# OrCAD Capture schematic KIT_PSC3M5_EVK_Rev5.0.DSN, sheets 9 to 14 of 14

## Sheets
9 08. COMMUNICATION AND PROGRAM: size A4
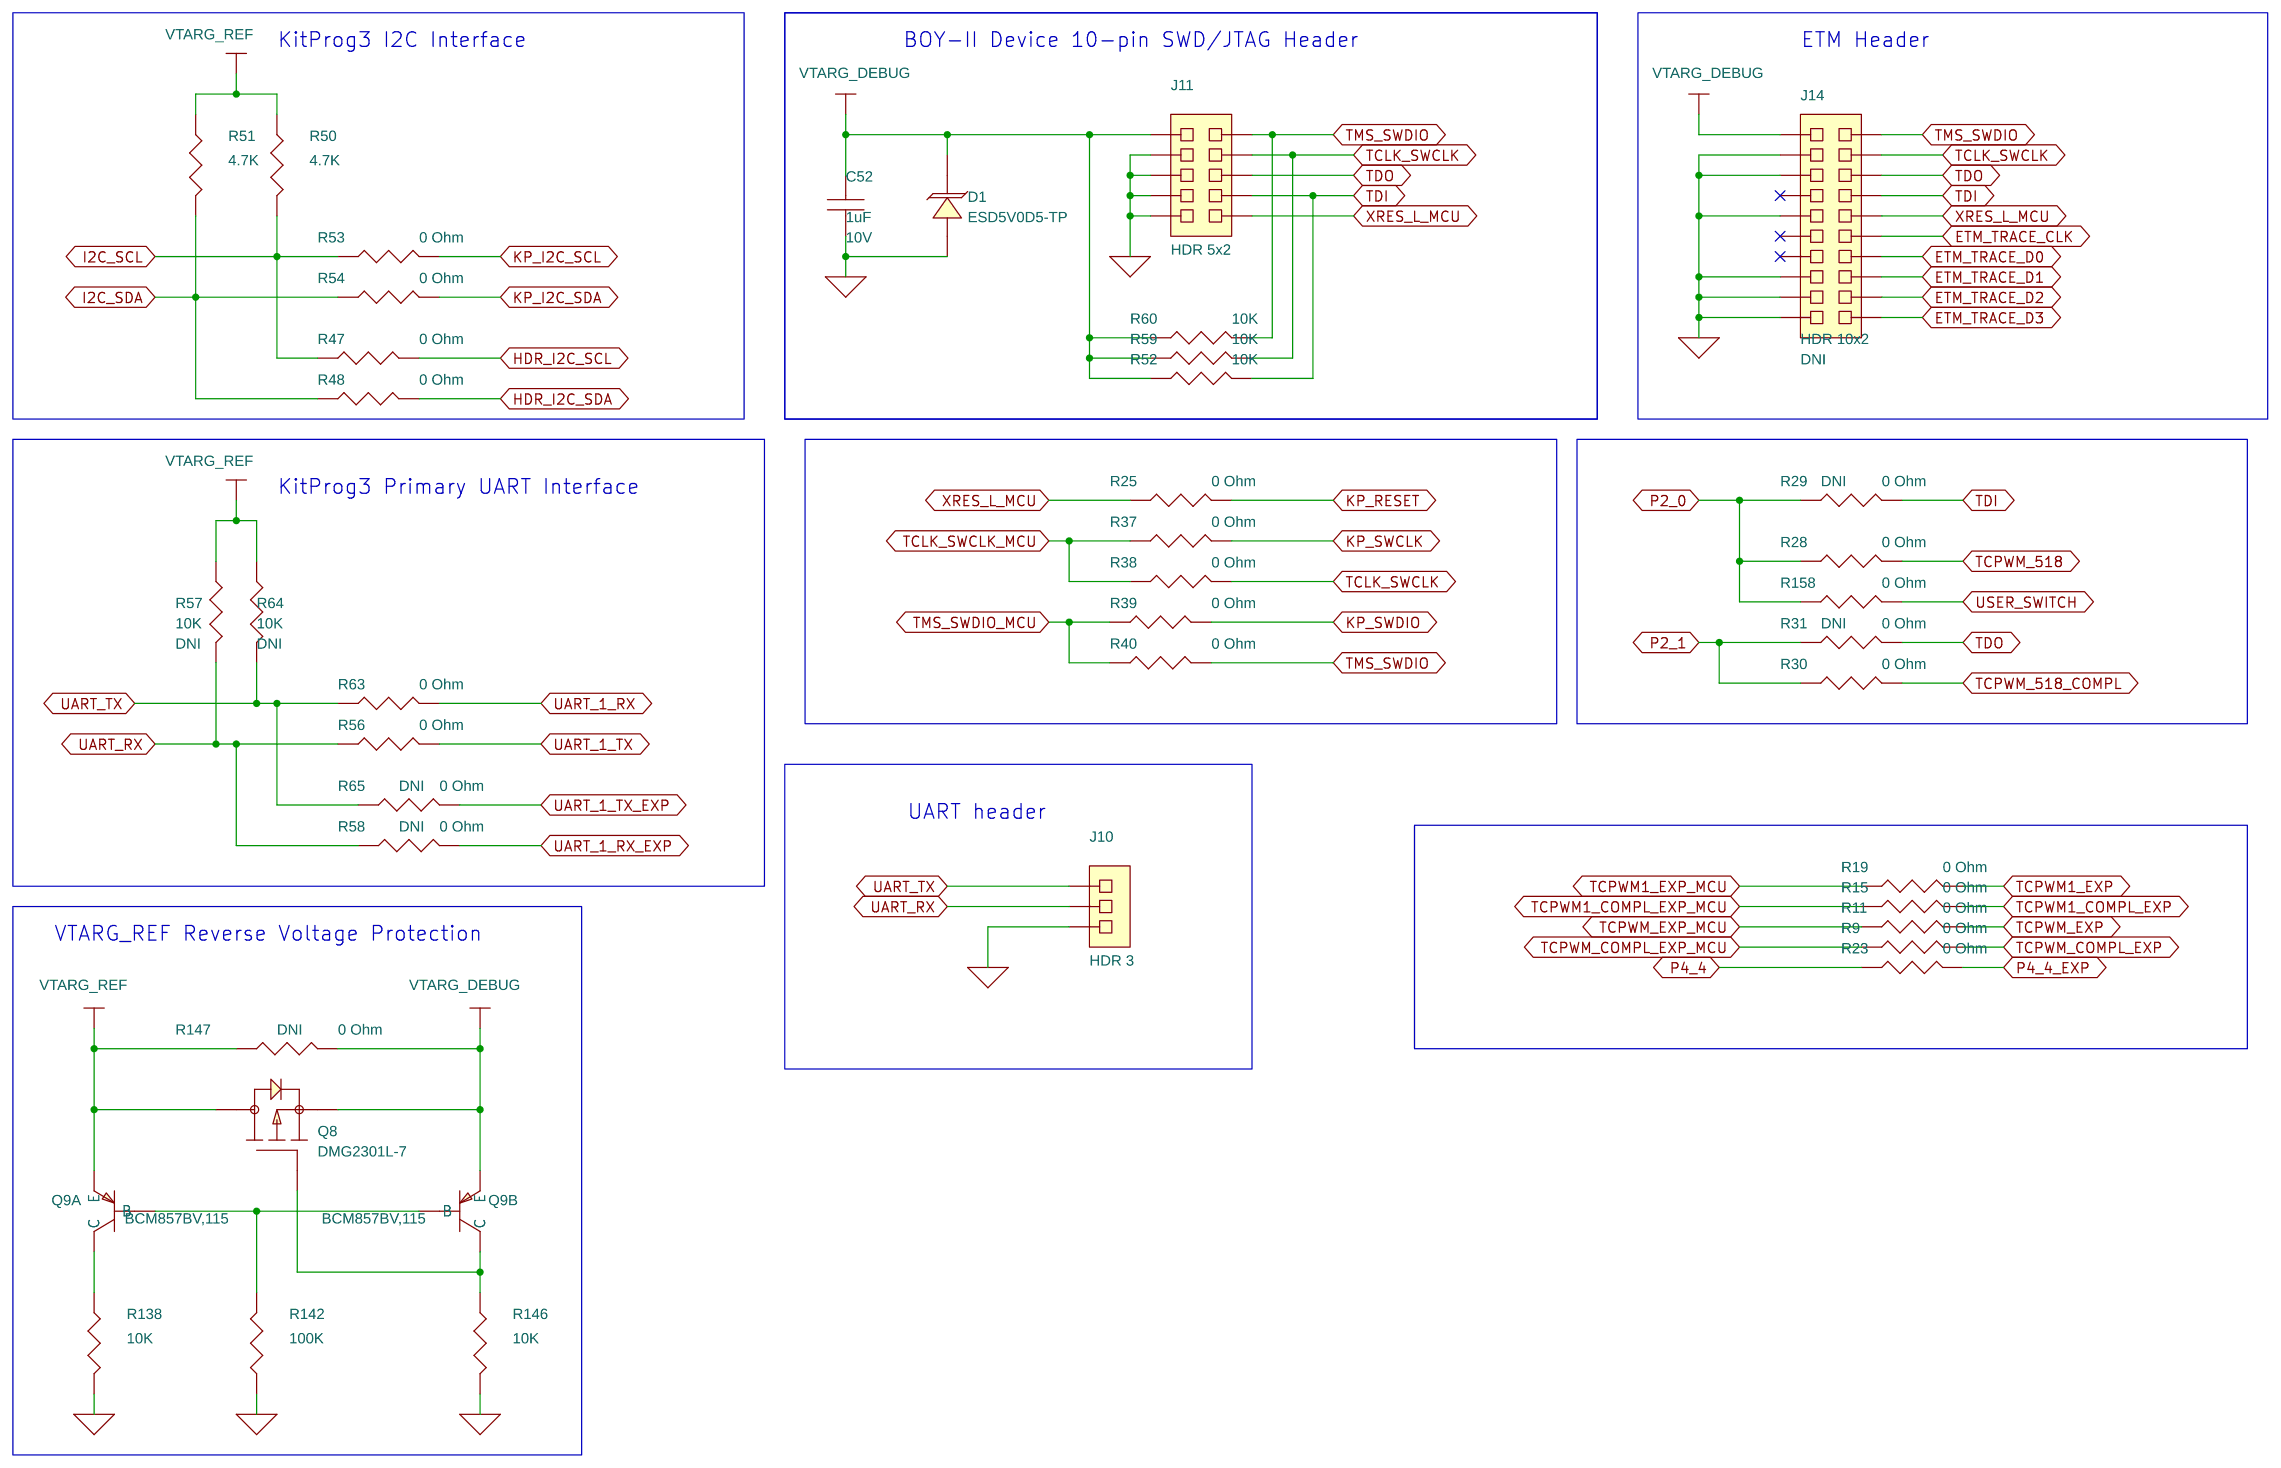
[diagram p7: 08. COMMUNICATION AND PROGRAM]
10 09. CAN INTERFACE: size A4
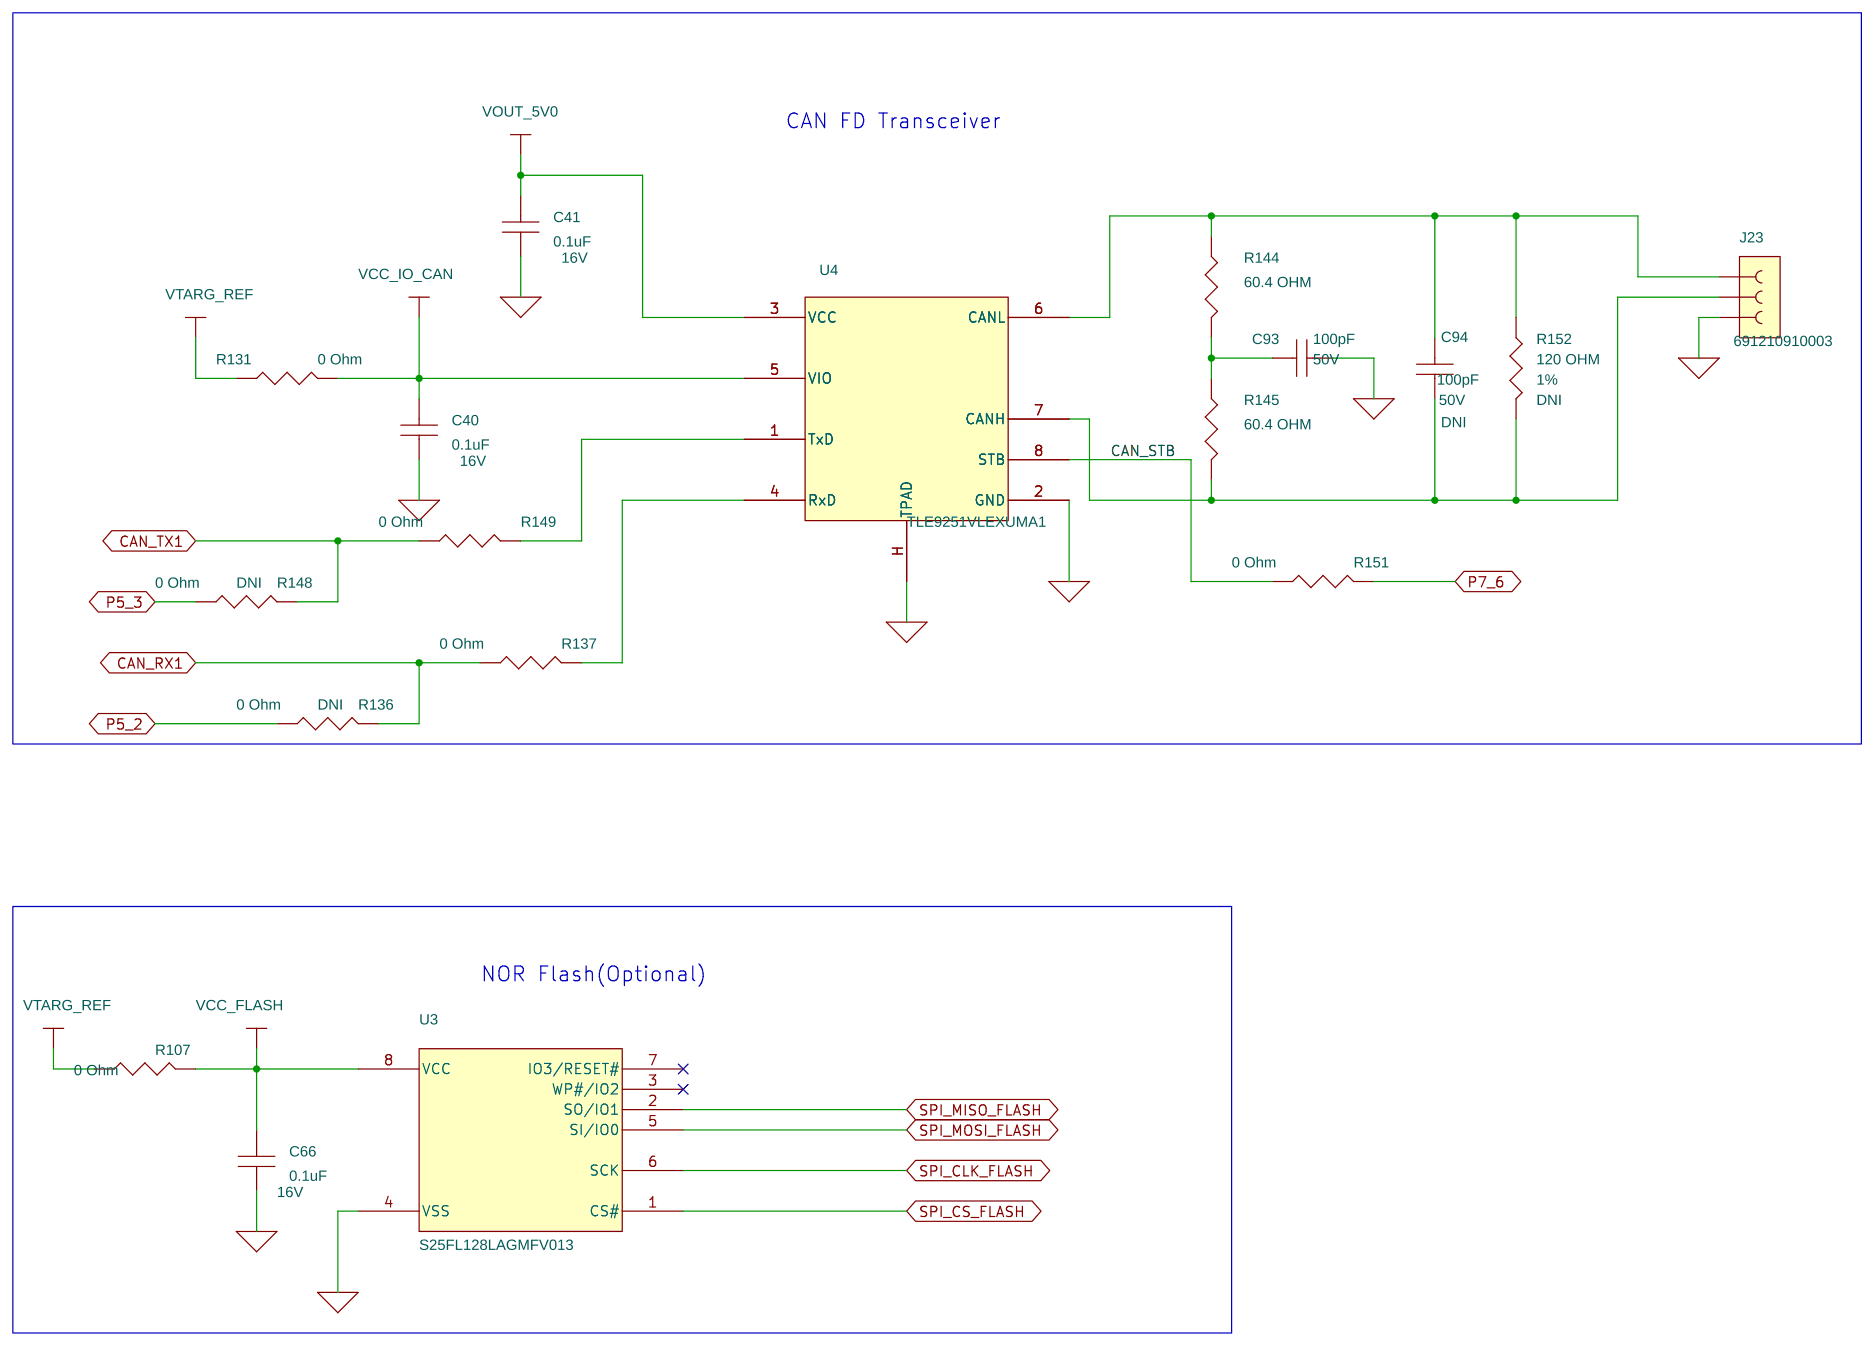
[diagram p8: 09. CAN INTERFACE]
11 10. INTERFACE HEADERS: size A4
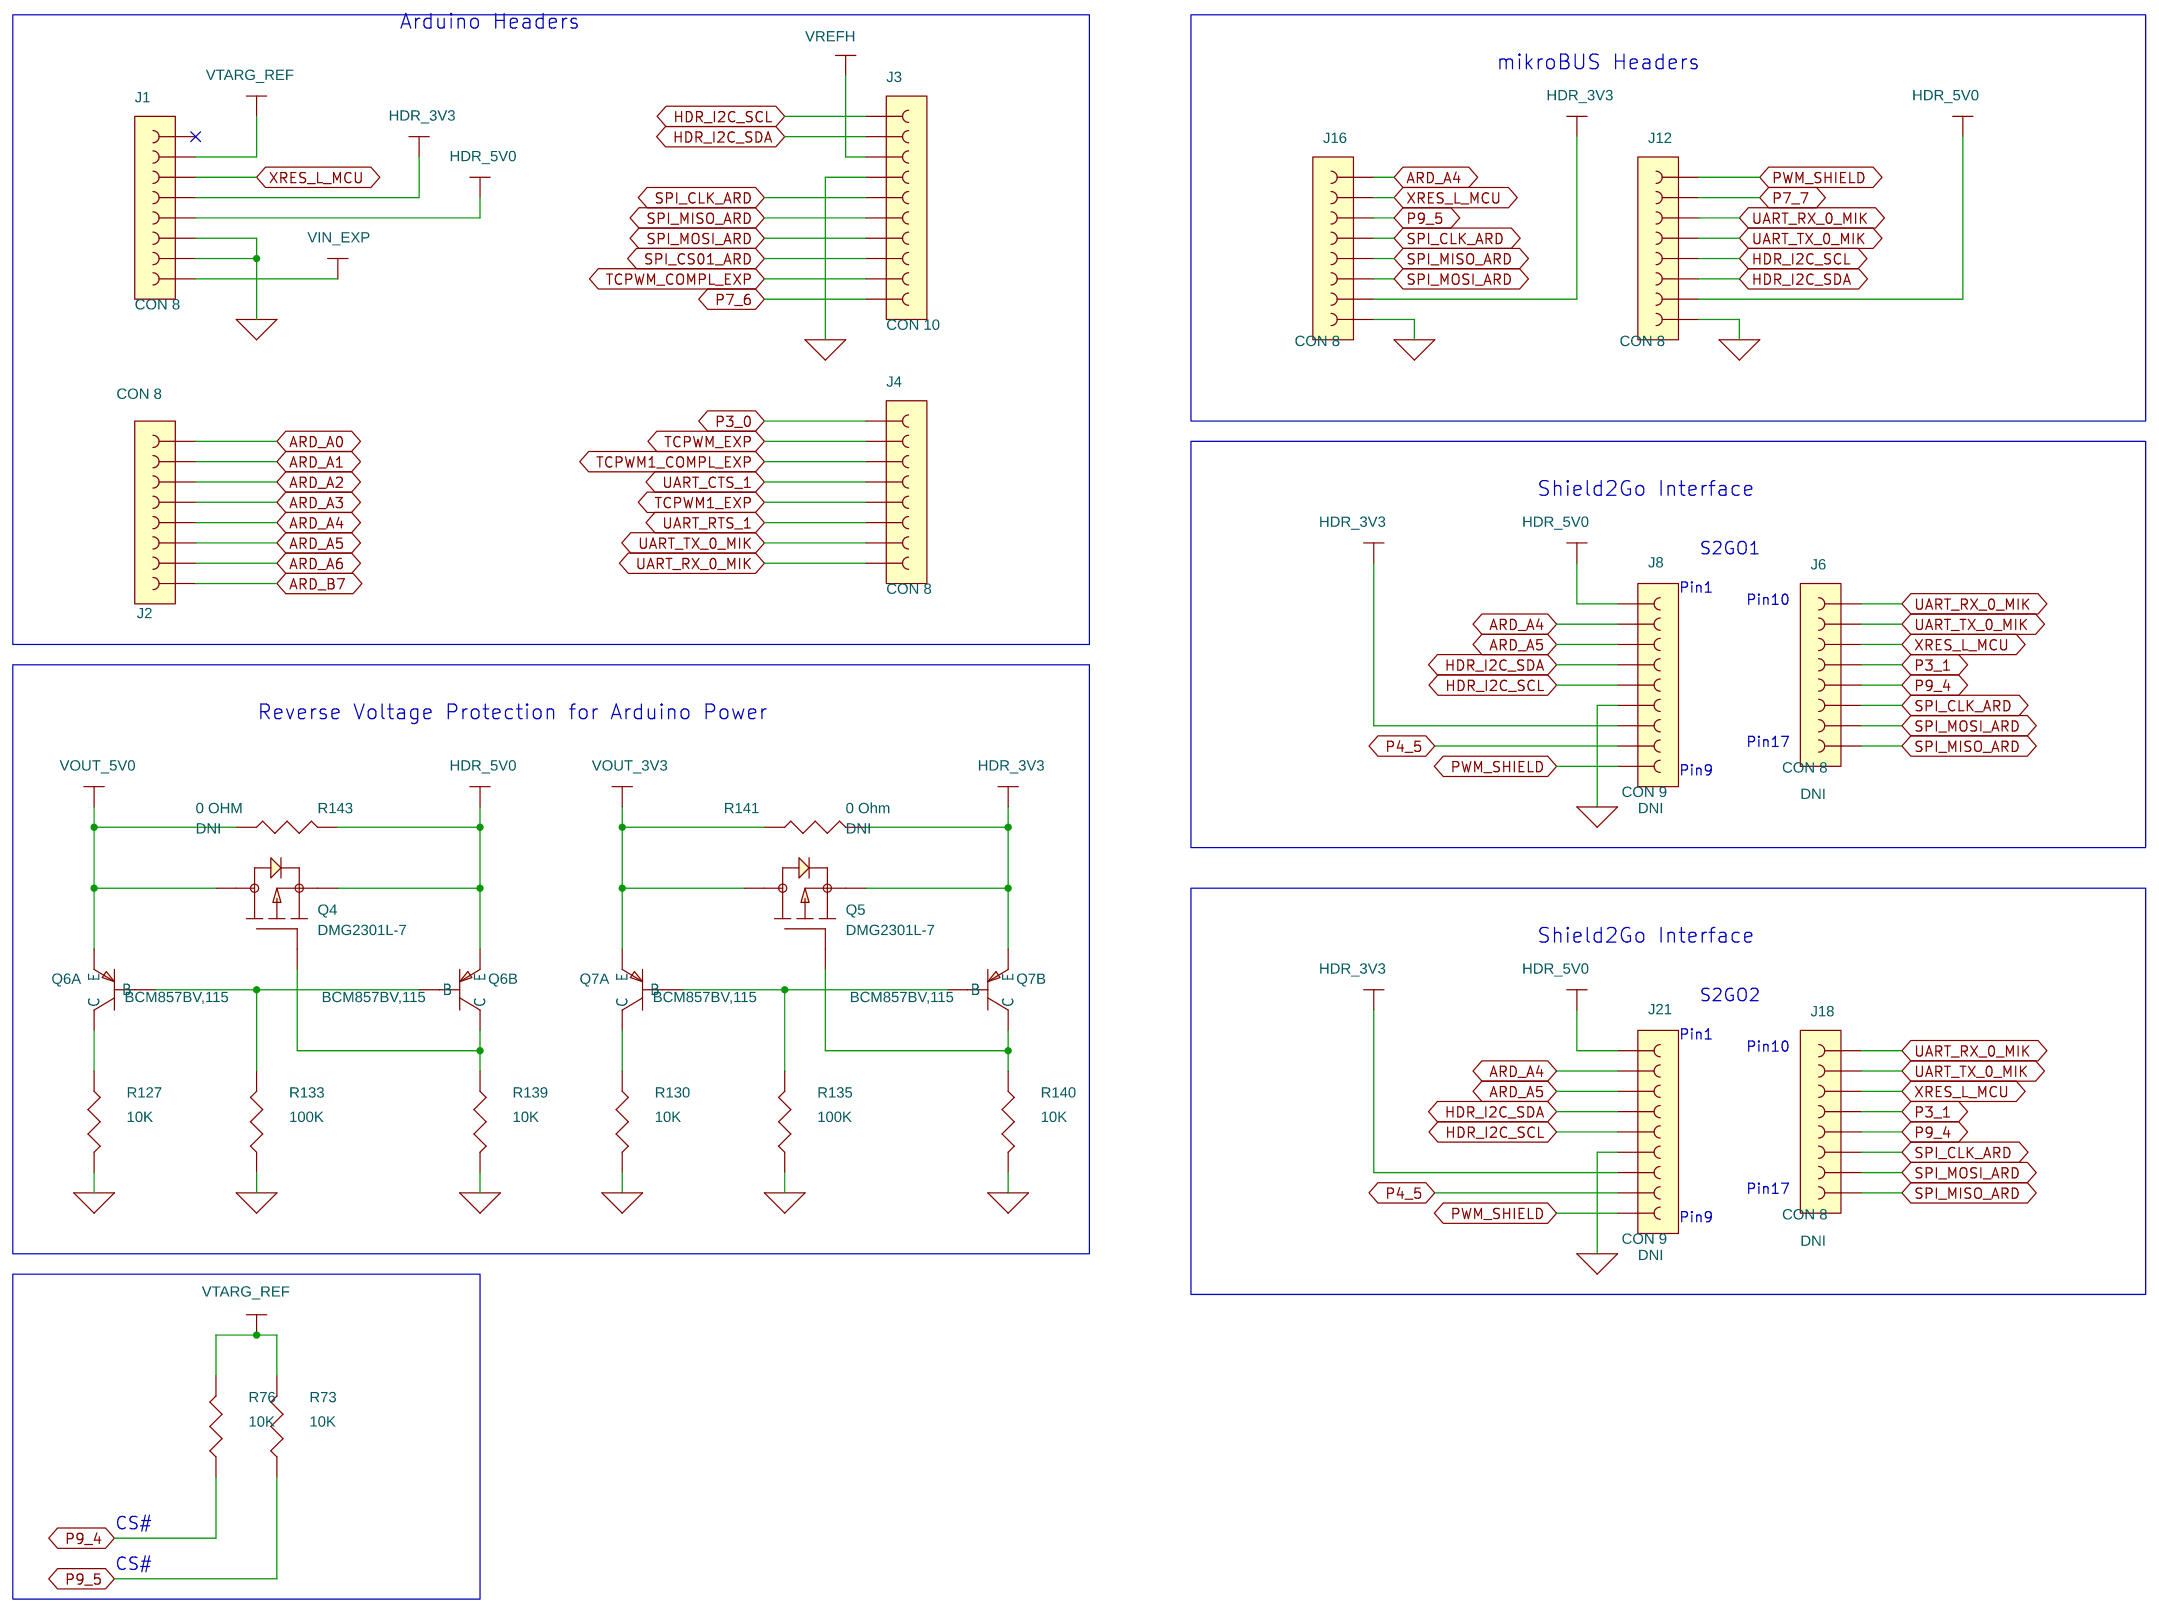
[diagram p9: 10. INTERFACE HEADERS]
12 11. EXPANSION HEADERS & BUTTONS: size A4
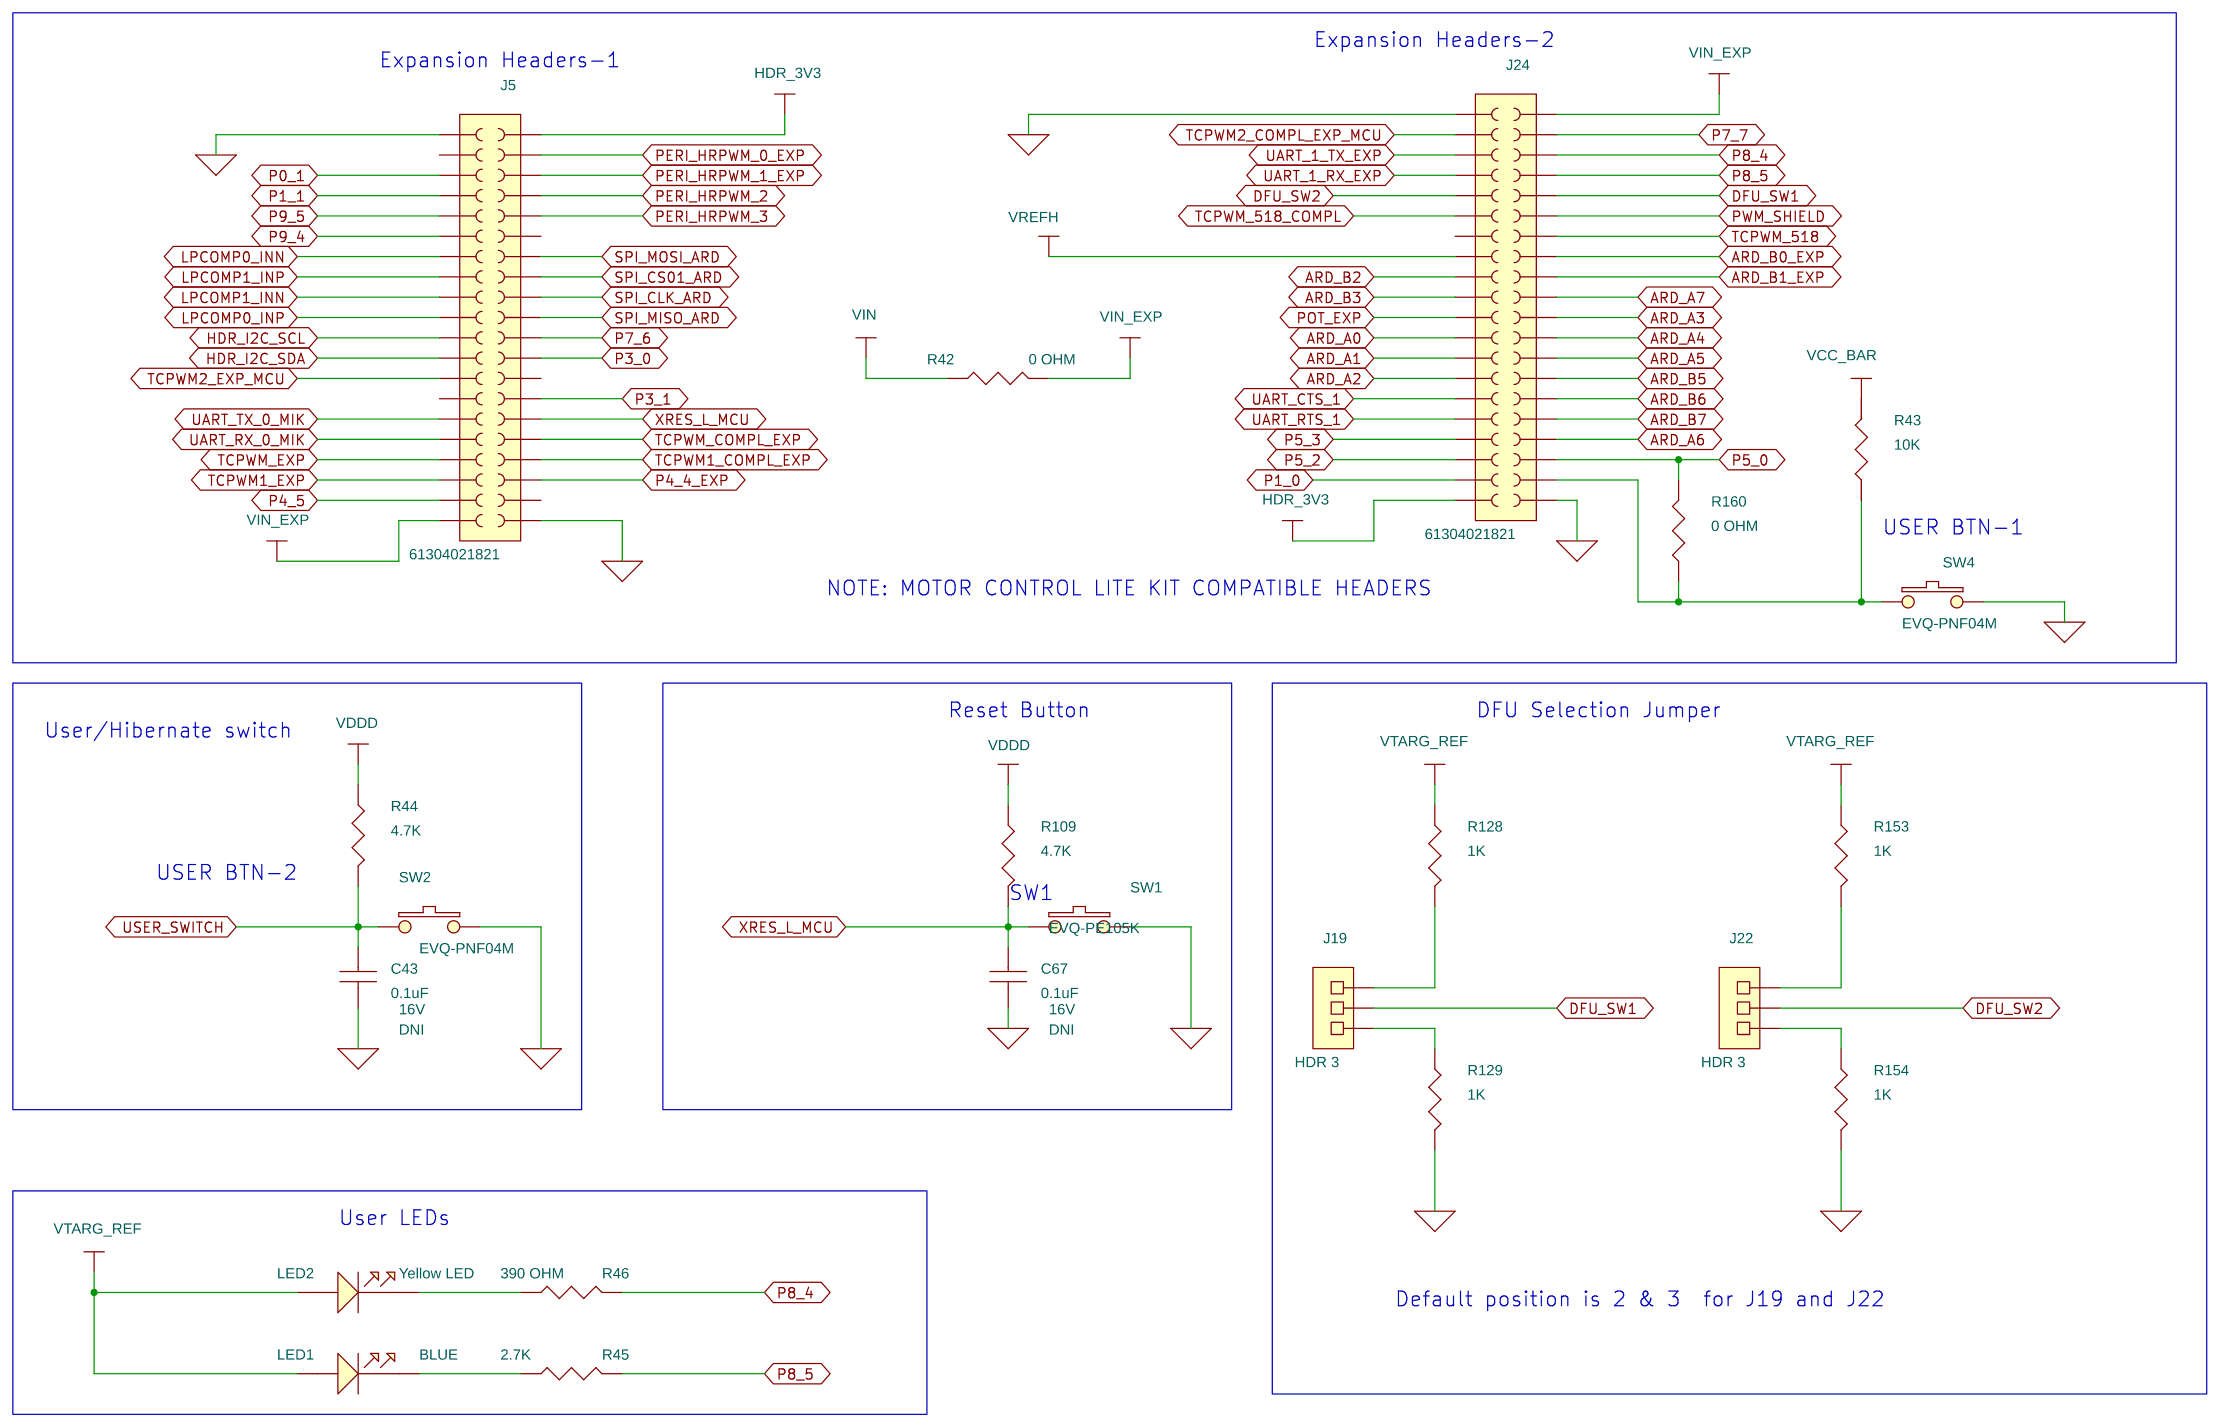
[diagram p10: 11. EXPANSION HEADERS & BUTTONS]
13 12. HRPWM OUTPUT AND POT: size A4
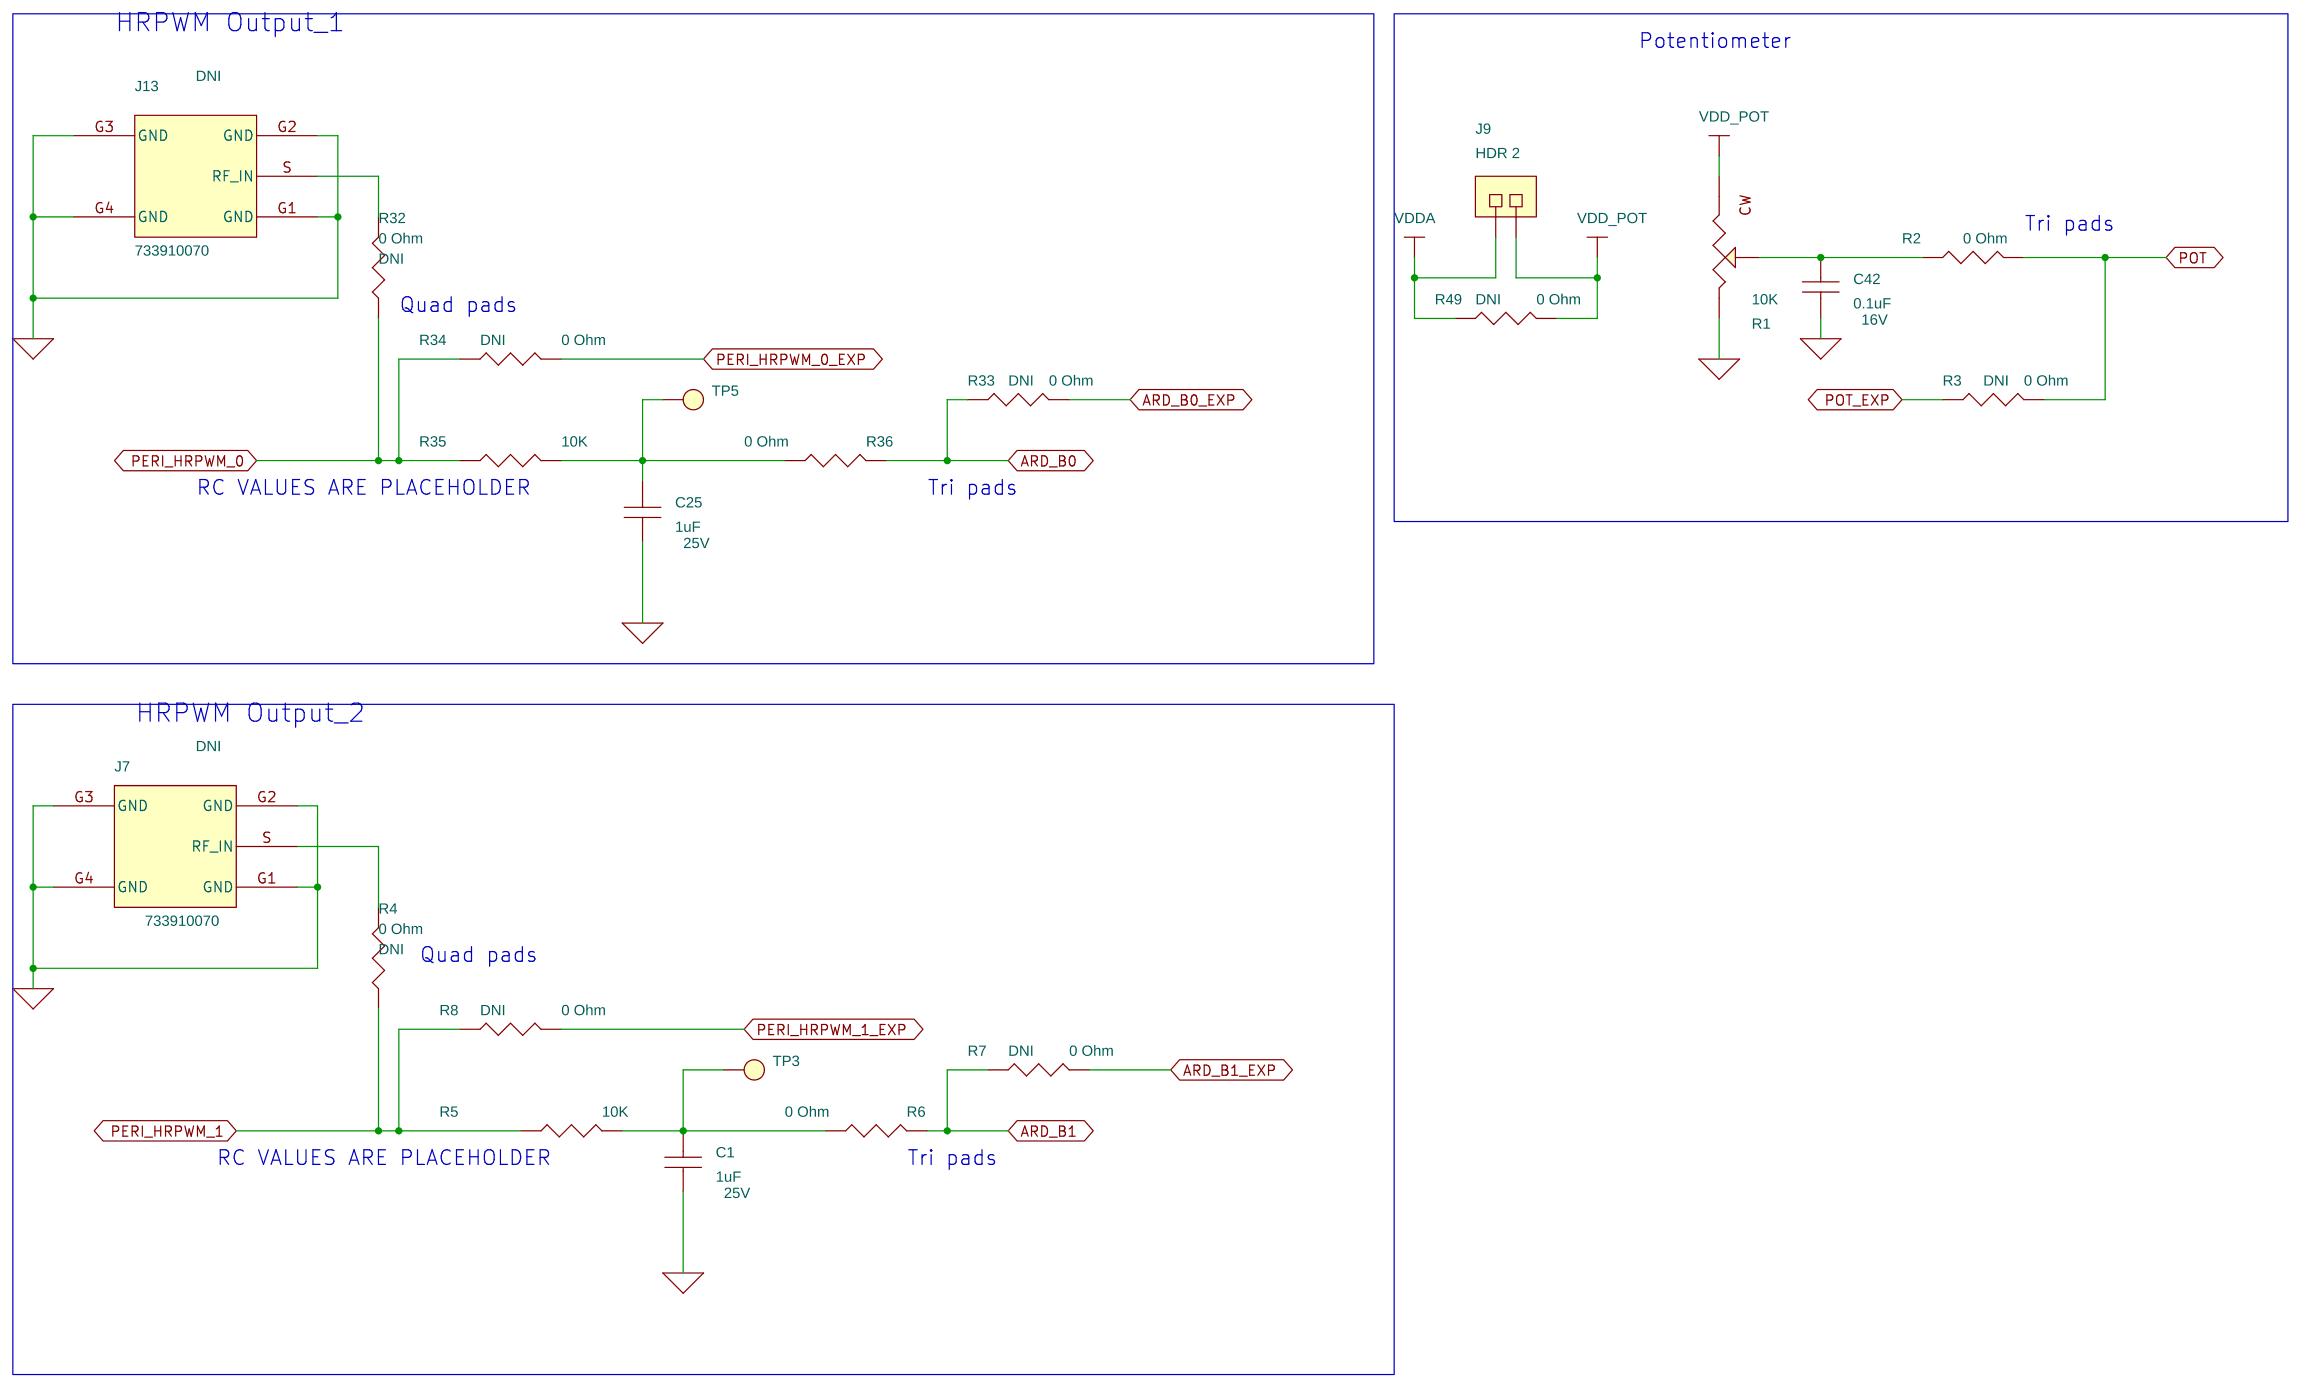
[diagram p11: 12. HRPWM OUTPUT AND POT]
14 14. REVISION HISTORY
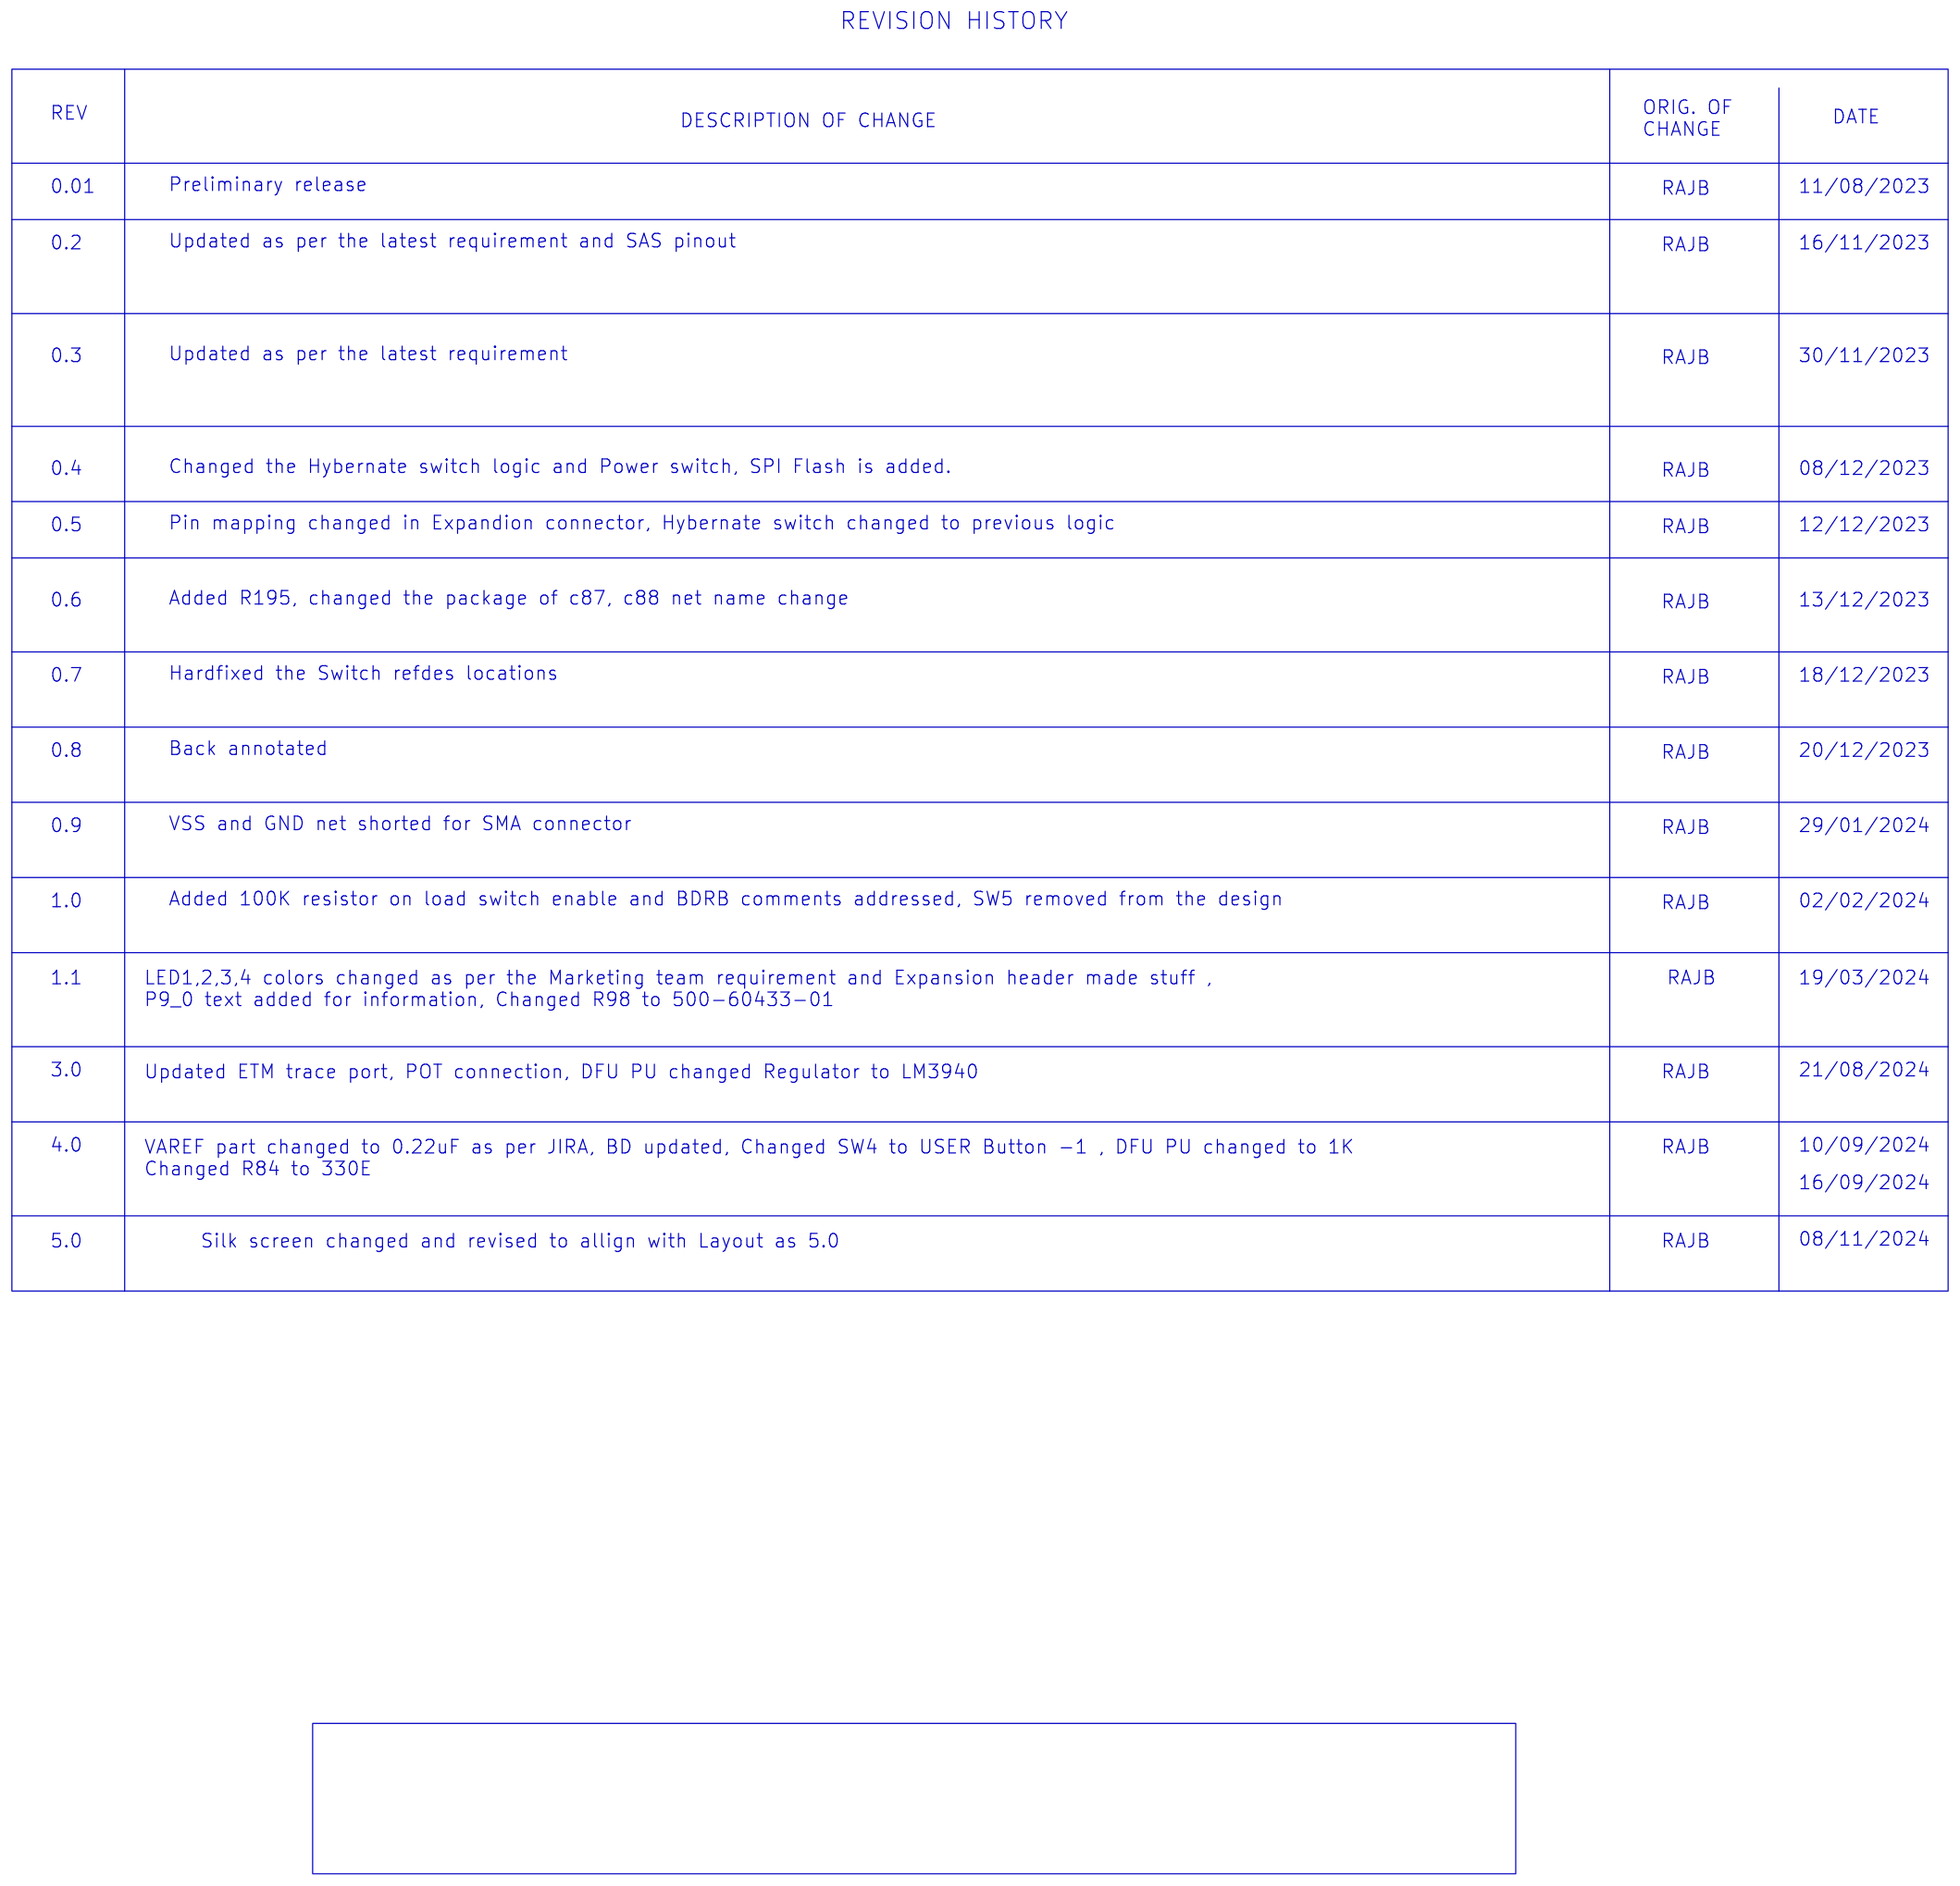
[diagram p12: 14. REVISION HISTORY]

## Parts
sheet 08. COMMUNICATION AND PROGRAM
C52  1uF  [CAPC1005_0402N]
D1  ESD5V0D5-TP  [sodfl1608x77m]
J10  HDR 3  [CTST254P1X03_W260]
J11  HDR 5x2  [FCI_20021521-00010T1LF]
J14  HDR 10x2  [CNC_3220-20-0100-00]
Q8  DMG2301L-7  [SOT23_G_S_D-DIODES]
Q9  BCM857BV,115  [SOT666_6N-NXP]  (sections A,B)
R9  0 Ohm  [RESC1608_0603N]
R11  0 Ohm  [RESC1608_0603N]
R15  0 Ohm  [RESC1608_0603N]
R19  0 Ohm  [RESC1608_0603N]
R23  0 Ohm  [RESC1608_0603N]
R25  0 Ohm  [RESC1608_0603N]
R28  0 Ohm  [RESC1608_0603N]
R29  0 Ohm  [RESC1608_0603N]
R30  0 Ohm  [RESC1608_0603N]
R31  0 Ohm  [RESC1608_0603N]
R37  0 Ohm  [RESC1608_0603N]
R38  0 Ohm  [RESC1608_0603N]
R39  0 Ohm  [RESC1608_0603N]
R40  0 Ohm  [RESC1608_0603N]
R47  0 Ohm  [RESC1608_0603N]
R48  0 Ohm  [RESC1608_0603N]
R50  4.7K  [RESC1005_0402N]
R51  4.7K  [RESC1005_0402N]
R52  10K  [RESC1608_0603N]
R53  0 Ohm  [RESC1608_0603N]
R54  0 Ohm  [RESC1608_0603N]
R56  0 Ohm  [RESC1608_0603N]
R57  10K  [RESC1608_0603N]
R58  0 Ohm  [RESC1608_0603N]
R59  10K  [RESC1608_0603N]
R60  10K  [RESC1608_0603N]
R63  0 Ohm  [RESC1608_0603N]
R64  10K  [RESC1608_0603N]
R65  0 Ohm  [RESC1608_0603N]
R138  10K  [RESC1005_0402N]
R142  100K  [RESC1005_0402N]
R146  10K  [RESC1005_0402N]
R147  0 Ohm  [RESC1608_0603N]
R158  0 Ohm  [RESC1608_0603N]
sheet 09. CAN INTERFACE
C40  0.1uF  [CAPC1005_0402N]
C41  0.1uF  [CAPC1005_0402N]
C66  0.1uF  [CAPC1005_0402N]
C93  100pF  [CAPC1005_0402N]
C94  100pF  [CAPC1005_0402N]
J23  691210910003  [OST_OSTVN03A150]
R107  0 Ohm  [RESC1608_0603N]
R131  0 Ohm  [RESC1608_0603N]
R136  0 Ohm  [RESC1608_0603N]
R137  0 Ohm  [RESC1608_0603N]
R144  60.4 OHM  [RESC1005_0402N]
R145  60.4 OHM  [RESC1005_0402N]
R148  0 Ohm  [RESC1608_0603N]
R149  0 Ohm  [RESC1608_0603N]
R151  0 Ohm  [RESC1608_0603N]
R152  120 OHM  [RESC1005_0402N]
U3  S25FL128LAGMFV013  [SOIC127P800X216-8N]
U4  TLE9251VLEXUMA1  [SON65P300X300X110-8N_TP]
sheet 10. INTERFACE HEADERS
J1  CON 8  [RTST254P1X08_W265]
J2  CON 8  [RTST254P1X08_W265]
J3  CON 10  [RTST254P1X10_W265]
J4  CON 8  [RTST254P1X08_W265]
J6  CON 8  [RTST254P1X08_W265_VER1]
J8  CON 9  [SULLINS_PPPC091LFBN-RC_VER1]
J12  CON 8  [RTST254P1X08_W265]
J16  CON 8  [RTST254P1X08_W265]
J18  CON 8  [RTST254P1X08_W265_VER1]
J21  CON 9  [SULLINS_PPPC091LFBN-RC_VER1]
Q4  DMG2301L-7  [SOT23_G_S_D-DIODES]
Q5  DMG2301L-7  [SOT23_G_S_D-DIODES]
Q6  BCM857BV,115  [SOT666_6N-NXP]  (sections A,B)
Q7  BCM857BV,115  [SOT666_6N-NXP]  (sections A,B)
R73  10K  [RESC1608_0603N]
R76  10K  [RESC1608_0603N]
R127  10K  [RESC1005_0402N]
R130  10K  [RESC1005_0402N]
R133  100K  [RESC1005_0402N]
R135  100K  [RESC1005_0402N]
R139  10K  [RESC1005_0402N]
R140  10K  [RESC1005_0402N]
R141  0 Ohm  [RESC1608_0603N]
R143  0 OHM  [RESC2012X60N]
sheet 11. EXPANSION HEADERS & BUTTONS
C43  0.1uF  [CAPC1005_0402N]
C67  0.1uF  [CAPC1005_0402N]
J5  61304021821  [WURTH_61304021821]
J19  HDR 3  [CTST254P1X03_W260]
J22  HDR 3  [CTST254P1X03_W260]
J24  61304021821  [WURTH_61304021821]
LED1  BLUE  [LEDC2012_0805_BLUE]
LED2  Yellow LED  [LEDC2012_0805]
R42  0 OHM  [RESC2012X60N]
R43  10K  [RESC1608_0603N]
R44  4.7K  [RESC1005_0402N]
R45  2.7K  [RESC1005_0402N]
R46  390 OHM  [RESC1005_0402N]
R109  4.7K  [RESC1005_0402N]
R128  1K  [RESC1005_0402N]
R129  1K  [RESC1005_0402N]
R153  1K  [RESC1005_0402N]
R154  1K  [RESC1005_0402N]
R160  0 OHM  [RESC2012X60N]
SW1  EVQ-PE105K  [SW_EVQ-PE105K]
SW2  EVQ-PNF04M  [SW_EVQ-PE105K]
SW4  EVQ-PNF04M  [SW_EVQ-PE105K]
sheet 12. HRPWM OUTPUT AND POT
C1  1uF  [CAPC1608_0603N]
C25  1uF  [CAPC1608_0603N]
C42  0.1uF  [CAPC1005_0402N]
J7  733910070  [MOL_SMA73391007X]
J9  HDR 2  [CTST254P1X02_W260]
J13  733910070  [MOL_SMA73391007X]
R1  10K  [TRIM_3386P-1-103TLF]
R2  0 Ohm  [RESC1608_0603N]
R3  0 Ohm  [RESC1608_0603N]
R4  0 Ohm  [RESC1608_0603N]
R5  10K  [RESC1608_0603N]
R6  0 Ohm  [RESC1608_0603N]
R7  0 Ohm  [RESC1608_0603N]
R8  0 Ohm  [RESC1608_0603N]
R32  0 Ohm  [RESC1608_0603N]
R33  0 Ohm  [RESC1608_0603N]
R34  0 Ohm  [RESC1608_0603N]
R35  10K  [RESC1608_0603N]
R36  0 Ohm  [RESC1608_0603N]
R49  0 Ohm  [RESC1608_0603N]
TP3  TP_SMD  [tp102c]
TP5  TP_SMD  [tp102c]

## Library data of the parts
C52 = CAP-NP: CAP, CER, 1uF, 20%, 10V, X5R, 0402; Approved: Approved; CY_PN: 510-60877-01; Device_File: 510-60877-01; Dielectric: X5R; FPLIST: CAPC1005_0402N,CAPC1005_0402M; Lifecycle: Active; Manufacturer: Wurth; Manufacturer_PN: 885012105012; Operating_Temp: -55°C ~ 85°C; Package: 0402; Part_Status: In Prod; Tolerance: 20%; Voltage: 10V
D1 = DIO-TVS: DIO, TVS, UNIDIR, 5V, 18.6V, 174W, SOD-523; CY_PN: 530-60165-01; Device File: 530-60165-01; Manufacturer: MCC
J10 J19 J22 = PLG-3-J: CONN, HDR, MALE, SINGLE, 3POS, 2.54mm, GOLD, STR, TH; CY_PN: 720-60018-01; Conatct_Length: 3.05mm; Contact_Finish: GOLD; Current_Rating: 3A; Device File: 720-60018-01; Device_File: 720-60018-01; Lifecycle: Active; Manufacturer: Wurth; Manufacturer_PN: 61300311121; Mated_Height: 5.84mm; Operating_Temp: -40°C to 105°C; Part_Status: InProd; Pin_Pitch: 2.54mm; Pins: 3; Rows: 1; Shrouding: Unshrouded
J11 = PLG-10-ODD-EVEN-J: CONN, BOX, MALE, DUAL, 10POS, 1.27mm, GOLD, STR, SMD; CY_PN: 720-60192-01; Conatct_Length: TBD; Contact_Finish: GOLD; Current_Rating: 1A; Device_File: 720-60192-01; Lifecycle: Active; Manufacturer: FCI; Manufacturer_PN: 20021521-00010T1LF; Mated_Height: 5.6mm; Operating_Temp: -40°C to 85°C; Part_Status: InProd; Pin_Pitch: 1.27mm; Pins: 10; Row_pitch: 1.27mm; Rows: 2; Shrouding: Shrouded
J14 = PLG-20-ODD-EVEN-J: CONN, BOX, MALE, DUAL, 20POS, 1.27mm, GOLD, STR, TH; CY_PN: 720-60390-01; Conatct_Length: TBD; Contact_Finish: GOLD; Current_Rating: 1A; DNI: DNI; Device File: 720-60390-01; Device_File: 720-60390-01; Lifecycle: Active; Manufacturer: CNC Tech; Manufacturer_PN: 3220-20-0100-00; Mated_Height: 5.4mm; Operating_Temp: -40°C to 105°C; Part_Status: In Prod; Pin_Pitch: 1.27; Pins: 20; Row_pitch: 1.27; Rows: 2; Shrouding: Shrouded
Q4 Q5 Q8 = FET-MOS-P: FET, MOSFET, P-CH, 20V, 3A, 1.5W, SOT-23; CY_PN: 532-60072-01; Current: 3A; Device File: 532-60072-01; Manufacturer: Diodes Inc; Power: 1.5W; Voltage: 20V
Q6 Q7 Q9 = PNP-PNP-E1B1C2E2B2C1: TRANS, DUAL, PNP, 45V, 0.1A, 0.2W, SOT-666; CY_PN: 531-60029-01; Current: 0.1A; Device File: 531-60029-01; Manufacturer: NXP; Power: 0.2W; Voltage: 45V
R2 R6 R9 R11 R15 R19 R23 R25 R28 R30 R36-R40 R47 R48 R53 R54 R56 R63 R107 R131 R137 R149 R151 R158 = RES: RES, Fixed, 0 OHM, JUMPER, 1/10W, 0603; Approved: Approved; CY_PN: 500-60037-01; Device_File: 500-60037-01; FPLIST: RESC1608_0603N,RESC1608_0603Q,RESC1608_0603M; Lifecycle: Active; Manufacturer: Wurth; Manufacturer_PN: 560112116001; Operating_Temp: -55°C ~ 155°C; Package: 0603; Part_Status: In Prod; Rating: 1/10W; Tolerance: JUMPER
R3 R4 R7 R8 R29 R31-R34 R49 R58 R65 R136 R141 R147 R148 = RES: RES, Fixed, 0 OHM, JUMPER, 1/10W, 0603; Approved: Approved; CY_PN: 500-60037-01; DNI: DNI; Device_File: 500-60037-01; FPLIST: RESC1608_0603N,RESC1608_0603Q,RESC1608_0603M; Lifecycle: Active; Manufacturer: Wurth; Manufacturer_PN: 560112116001; Operating_Temp: -55°C ~ 155°C; Package: 0603; Part_Status: In Prod; Rating: 1/10W; Tolerance: JUMPER
R44 R50 R51 R109 = RES: RES, FIXED, 4.7K OHM, 5%, 100PPM, 1/10W, 0402; Approved: Approved; CY_PN: 500-61391-01; Device_File: 500-61391-01; FPLIST: RESC1005_0402N,RESC1005_0402M; Lifecycle: Active; Manufacturer: Wurth; Manufacturer_PN: 560112110018; Operating_Temp: -55°C ~ 155°C; Package: 0402; Part_Status: unrel; Rating: 1/10W; Tolerance: 5%
R52 R59 R60 = RES: RES, Fixed, 10K, 1%, 1/10W, 0603; Approved: Approved; CY_PN: 500-60043-01; Device_File: 500-60043-01; FPLIST: RESC1608_0603N,RESC1608_0603Q,RESC1608_0603M; Lifecycle: Active; Manufacturer: Wurth; Manufacturer_PN: 560112116005; Operating_Temp: -55°C ~ 155°C; Package: 0603; Part_Status: In Prod; Rating: 1/10W; Tolerance: 1%
R57 R64 = RES: RES, Fixed, 10K, 1%, 1/10W, 0603; Approved: Approved; CY_PN: 500-60043-01; DNI: DNI; Device_File: 500-60043-01; FPLIST: RESC1608_0603N,RESC1608_0603Q,RESC1608_0603M; Lifecycle: Active; Manufacturer: Wurth; Manufacturer_PN: 560112116005; Operating_Temp: -55°C ~ 155°C; Package: 0603; Part_Status: In Prod; Rating: 1/10W; Tolerance: 1%
R127 R130 R138-R140 R146 = RES: RES, FIXED, 10K OHM, 5%, 1/10W, 0402; Approved: Approved; CY_PN: 500-60470-01; Device_File: 500-60470-01; FPLIST: RESC1005_0402N,RESC1005_0402M; Lifecycle: Active; Manufacturer: Wurth; Manufacturer_PN: 560112110006; Operating_Temp: -55°C ~ 155°C; Package: 0402; Part_Status: In Prod; Rating: 1/10W; Tolerance: 5%
R133 R135 R142 = RES: RES, FIXED, 100K OHM, 5%, 100PPM, 1/10W, 0402; Approved: Approved; CY_PN: 500-61389-01; Device_File: 500-61389-01; FPLIST: RESC1005_0402N,RESC1005_0402M; Lifecycle: Active; Manufacturer: Wurth; Manufacturer_PN: 560112110063; Operating_Temp: -55°C ~ 155°C; Package: 0402; Part_Status: unrel; Rating: 1/10W; Tolerance: 5%
C40-C42 C66 = CAP-NP: CAP, CER, 0.1uF, 10%, X7R, 16V, 0402; Approved: Approved; CY_PN: 510-60878-01; Device_File: 510-60878-01; Dielectric: X7R; FPLIST: CAPC1005_0402N,CAPC1005_0402M; Lifecycle: Active; Manufacturer: Wurth; Manufacturer_PN: 885012205037; Operating_Temp: -55°C ~ 125°C; Package: 0402; Part_Status: In prod; Tolerance: 10%; Voltage: 16V
C93 = CAP-NP: CAP, CER, 100PF, 5%, C0G, 50V, 0402; Approved: Approved; CY_PN: 510-60558-01; Device_File: 510-60558-01; Dielectric: COG; FPLIST: CAPC1005_0402N,CAPC1005_0402M; Lifecycle: Active; Manufacturer: Wurth; Manufacturer_PN: 885012005061; Operating_Temp: -55°C ~ 125°C; Package: 0402; Part_Status: In Prod; Tolerance: 5%; Voltage: 50V
C94 = CAP-NP: CAP, CER, 100PF, 5%, C0G, 50V, 0402; CY_PN: 510-60558-01; DNI: DNI; Device_File: 510-60558-01; Dielectric: COG; FPLIST: CAPC1005_0402N,CAPC1005_0402M; Lifecycle: Active; Manufacturer: TDK; Manufacturer_PN: CGA2B2C0G1H101J050BA; Operating_Temp: -55°C to 125°C; Package: 0402; Part_Status: Unrel; SIGNAL_MODEL: CAP-NP_CAPC1005_0402N_DISCRETE_100PF_100pF; Tolerance: 5%; Voltage: 50V
J23 = OSTVN03A150: CONN, TERMINAL BLOCK, 3POS, 2.54mm, 150VAC 6A, PTH; CY_PN: 720-60536-01; Manufacturer: Wurth
R144 R145 = RES: RES, FIXED, 60.4 OHM, 1%, 1/10W, 0402; Approved: Approved; CY_PN: 500-61410-01; Device_File: 500-61410-01; FPLIST: RESC1005_0402N,RESC1005_0402M; Lifecycle: Active; Manufacturer: Wurth; Manufacturer_PN: 560112110170; Operating_Temp: -55°C ~ 155°C; Package: 0402; Part_Status: unrel; Rating: 1/10W; Tolerance: 1%
R152 = ERJ-3GEYJ121V: RES, 120 OHM, 1%, 1/16W, 0402; CY_PN: 500-61089-01; DNI: DNI; Manufacturer: Yageo; Manufacturer_PN: RC0402FR-07120RL; SIGNAL_MODEL: ERJ-3GEYJ121V_RESC1005_0402N_120_OHM_120_OHM; Tolerance: 1%
U3 = IC_S25FL128LAG: IC,Infineon, FLASH, 128MBIT, SPI/QUAD, 8SOIC; Approved: Approved; Lifecycle: Active; Manufacturer: Infineon; Operating_Temp: -40°C ~ 105°C; Operating_Voltage: 2.7 V to 3.6 V; Package: 8-SOIC-208 mil; Part_Status: Unrel
U4 = TLE9251VLE: IC, Transceiver, CAN-FD, 5Mbps, 4.5V-5.5V, TSON-8; Approved: Approved; CY_PN: 450-60400-01; Costing: CAN; Device_File: 450-60400-01; HARD_LOCATION: YES; Lifecycle: Active; Manufacturer: Infineon; Operating_Temp: -40°C to 150°C; Operating_Voltage: 4.5V-5.5V; Package: 8-TSON; Part_Status: Unrel
J1 J4 = SKT-8-ALT-J: CONN, HDR, FEMALE, SINGLE, 8POS, 2.54mm, GOLD, STR, TH; CY_PN: 710-60025-01; Device File: 710-60025-01; HARD_LOCATION: YES; Manufacturer: Wurth; Manufacturer_PN: 61300811821
J2 = SKT-8-ALT-J: CONN, HDR, FEMALE, SINGLE, 8POS, 2.54mm, GOLD, STR, TH; CY_PN: 710-60025-01; Costing: Arduino; Device File: 710-60025-01; HARD_LOCATION: YES; Manufacturer: Wurth; Manufacturer_PN: 61300811821
J3 = SKT-10-J: CONN, HDR, FEMALE, SINGLE, 10POS, 2.54mm, GOLD, STR, TH; CY_PN: 710-60027-01; Device File: 710-60027-01; HARD_LOCATION: YES; Manufacturer: Wurth; Manufacturer_PN: 61301011821
J6 J18 = SKT-8-ALT-J: CONN, HDR, FEMALE, SINGLE, 8POS, 2.54mm, GOLD, STR, TH; CY_PN: 710-60025-01; Conatct_Length: TBD; Contact_Finish: GOLD; Costing: S2GO_HDR; Current_Rating: 3A; DNI: DNI; Device_File: 710-60025-01; Manufacturer: Wurth; Manufacturer_PN: 61300811821; Mated_Height: 8.5mm; Operating_Temp: -40°C to 125°C; Part_Status: In Prod; Pin_Pitch: 2.54; Pins: 8; Row_pitch: NA; Rows: 1; Shrouding: NA
J8 J21 = SKT-9-J: CONN, HDR, FEMALE, SINGLE, 9POS, 2.54mm, GOLD, STR, TH; Approved: Approved; CY_PN: 720-60578-01; Conatct_Length: 3.2mm; Contact_Finish: GOLD; Costing: S2GO_HDR; Current_Rating: 3A; DNI: DNI; Device_File: 720-60578-01; FPLIST: SULLINS_PPPC091LFBN-RC,SULLINS_PPPC091LFBN-RC_VER1; Lifecycle: Active; Manufacturer: Sullins; Manufacturer_PN: PPPC091LFBN-RC; Mated_Height: 8.51mm; Operating_Temp: -40°C to 105°C; Part_Status: Unrel; Pin_Pitch: 2.54MM; Pins: 9; Row_pitch: NA; Rows: 1; Shrouding: NA
J12 J16 = SKT-8-ALT-J: CONN, HDR, FEMALE, SINGLE, 8POS, 2.54mm, GOLD, STR, TH; CY_PN: 710-60025-01; Conatct_Length: TBD; Contact_Finish: GOLD; Costing: mikroBUS; Current_Rating: 3A; Device_File: 710-60025-01; Manufacturer: Wurth; Manufacturer_PN: 61300811821; Mated_Height: 8.5mm; Operating_Temp: -40°C to 125°C; Part_Status: In Prod; Pin_Pitch: 2.54; Pins: 8; Row_pitch: NA; Rows: 1; Shrouding: NA
R5 R35 R43 R73 R76 = RES: RES, Fixed, 10K OHM, 5%, 1/10W, 0603; Approved: Approved; CY_PN: 500-60045-01; Device_File: 500-60045-01; FPLIST: RESC1608_0603N,RESC1608_0603Q,RESC1608_0603M; Lifecycle: Active; Manufacturer: Wurth; Manufacturer_PN: 560112116012; Operating_Temp: -55°C ~ 155°C; Package: 0603; Part_Status: In Prod; Rating: 1/10W; Tolerance: 5%
R143 = RES: RES, 0 OHM, JUMPER, 2A, 0805; CY_PN: 500-61085-01; DNI: DNI; Manufacturer: Yageo; Manufacturer_PN: AC0805JR-070RL; Rating: 2A; Tolerance: JUMPER; Wattage: 1/8W
C43 C67 = CAP-NP: CAP, CER, 0.1uF, 10%, X7R, 16V, 0402; Approved: Approved; CY_PN: 510-60878-01; DNI: DNI; Device_File: 510-60878-01; Dielectric: X7R; FPLIST: CAPC1005_0402N,CAPC1005_0402M; Lifecycle: Active; Manufacturer: Wurth; Manufacturer_PN: 885012205037; Operating_Temp: -55°C ~ 125°C; Package: 0402; Part_Status: In prod; Tolerance: 10%; Voltage: 16V
J5 J24 = SKT-40-EVEN-ODD-J: CONN,RECEPTACLE, FEMALE, DUAL, 40POS, 2.54mm, GOLD, STR, PTH; Approved: Approved; CY_PN: 710-60143-01; Conatct_Length: 3.10mm; Contact_Finish: Gold; Current_Rating: 3A; Device_File: 710-60143-01; Lifecycle: Active; Manufacturer: Wurth; Mated_Height: NA; Operating_Temp: -40°C ~ 125°C; Part_Status: In Des; Pin_Pitch: 2.54mm; Pins: 40; Row_pitch: NA; Rows: 2; Shrouding: NA
LED1 = DIO-LED: LED, BLUE, CLEAR, 470NM, 2.65V, 0805; Approved: Approved; CY_PN: 534-60133-01; Device_File: 534-60133-01; Lifecycle: Active; Manufacturer: Kingbright; Manufacturer_PN: APT2012LVBC/D; Operating_Temp: -40°C ~ 85°C; Package: 0805; Part_Status: In Des; Rating: NA; Voltage: 2.65V
LED2 = DIO-LED: LED, YELLOW, CLEAR, 590nm, 120mcd, 2V, 0805; Approved: Approved; CY_PN: 534-60144-01; Device_File: 534-60144-01; Lifecycle: Active; Manufacturer: Wurth; Manufacturer_PN: 150080YS75000; Operating_Temp: -40°C ~ 85°C; Package: 0805; Part_Status: In Prod; Rating: 30mA; Voltage: 2V
R42 R160 = RES: RES, Fixed, 0 OHM, 0.05, 1/8W, 0805; CY_PN: 500-61085-01; Device_File: 500-61085-01; Lifecycle: Active; Manufacturer: Yageo; Manufacturer_PN: AC0805JR-070RL; Operating_Temp: -55°C to 155°C; Package: 0805; Part_Status: In Production; Rating: 1/8W
R45 = RES: RES, FIXED, 2.7K OHM, 1%, 1/10W, 0402; Approved: Approved; CY_PN: 500-61408-01; Device_File: 500-61408-01; FPLIST: RESC1005_0402N,RESC1005_0402M; Lifecycle: Active; Manufacturer: Wurth; Manufacturer_PN: 560112110266; Operating_Temp: -55°C ~ 155°C; Package: 0402; Part_Status: unrel; Rating: 1/10W; Tolerance: 1%
R46 = RES: RES, Fixed, 390 OHM, 5%, 1/10W, 0402; CY_PN: 500-60713-01; Device_File: 500-60713-01; FPLIST: RESC1005_0402N,RESC1005_0402M; Lifecycle: Active; Manufacturer: Panasonic; Manufacturer_PN: ERJ-2GEJ391X; Operating_Temp: -55°C to 155°C; Package: 0402; Part_Status: In Production; Rating: 1/10W; Tolerance: 5%
R128 R129 R153 R154 = RES: RES, Fixed, 1K, 1%, 1/8W, 0402; Approved: Approved; CY_PN: 500-61168-01; Device_File: 500-61168-01; FPLIST: RESC1005_0402N,RESC1005_0402M; Lifecycle: Active; Manufacturer: Vishay; Manufacturer_PN: RCC04021K00FKED; Operating_Temp: -55°C ~ 155°C; Package: 0402; Part_Status: In Des; Rating: 1/8W; Tolerance: 1%
SW1 = SWITCH-PB-A-B_3: SW, TACT, SPST-NO, 12V, 0.05A, STR, SMD; Actuator_Length: 1.5mm; CY_PN: 770-60006-01; Circuit: SPST-NO; Current_Rating: 0.05A; Device File: 770-60006-01; HARD_LOCATION: YES; Lifecycle: Active; Manufacturer: Panasonic; Operating_Force: 1N; Operating_Temp: -30°C to 85°C; Part_Status: In Prod; Pins: 2; Switch_Function: Off-Mom
SW2 = SWITCH-PB-1-2_4: SW, TACT, SPST-NO, 12V, 0.05A, STR, SMD; CY_PN: 770-60114-01; Device File: 770-60114-01; HARD_LOCATION: YES; Manufacturer: Panasonic
SW4 = SWITCH-PB-1-2_3: SW, TACT, SPST-NO, 12V, 0.05A, STR, SMD; CY_PN: 770-60114-01; Device File: 770-60114-01; HARD_LOCATION: YES; Manufacturer: Panasonic
C1 C25 = CAP-NP: CAP, CER, 1uF, 10%, X7R, 25V, 0603; Approved: Approved; CY_PN: 510-60064-01; Device_File: 510-60064-01; Dielectric: X7R; FPLIST: CAPC1608_0603N,CAPC1608_0603M; Lifecycle: Active; Manufacturer: Wurth; Manufacturer_PN: 885012206076; Operating_Temp: -55°C ~ 125°C; Package: 0603; Part_Status: Unrel; Tolerance: 10%; Voltage: 25V
J7 J13 = RF-4GND: CONN, SMA, FEMALE, JACK, 18GHz, 500V, 50 OHM, GOLD, STR, TH; Approved: Approved; CY_PN: 720-60558-01; Conatct_Length: NA; Contact_Finish: GOLD; Current_Rating: NA; DNI: DNI; Device_File: 720-60558-01; Lifecycle: Active; Manufacturer: Molex; Mated_Height: NA; Operating_Temp: -65°C to 165°C; Part_Status: Unrel; Pin_Pitch: NA; Pins: 5; Row_pitch: NA; Rows: NA; Shrouding: NA
J9 = PLG-2-J: CONN, HDR, MALE, SINGLE, 2POS, 2.54mm, GOLD, STR, TH; Approved: Approved; CY_PN: 720-60349-01; Conatct_Length: 6.0mm; Contact_Finish: GOLD; Current_Rating: 3A; Device_File: 720-60349-01; Lifecycle: Active; Manufacturer: Wurth; Manufacturer_PN: 61300211121; Mated_Height: 8.54mm; Operating_Temp: -40°C to 105°C; Part_Status: In Prod; Pin_Pitch: 2.54mm; Pins: 2; Row_pitch: NA; Rows: 1; Shrouding: Unshrouded
R1 = POT_1_2_3: POTENTIOMETER, 10K, 10%, 1/2W, TH; CY_PN: 500-60547-01; Description1: 1 Turn, Top Finger Adjustment, Sealed, PC Pins; Device_File: 500-60547-01; Lifecycle: Active; Manufacturer: Bourns; Manufacturer_PN: 3386P-1-103T; Operating_Temp: -55°C to 125°C; Package: TH; Part_Status: In Prod; Rating: 1/2W; Tolerance: 10%
TP3 TP5 = TP_SMD: TestPoint, PCB, Circle, 1mm, SMD; CY_PN: NA; DNI: DNI; Lifecycle: NA; Manufacturer: NA; Manufacturer_PN: NA; Part_Status: NA

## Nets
GND_SIGNAL: C1.1 C25.1 C40.1 C41.1 C42.2 C43.2 C52.2 C66.1 C67.2 C93.2 D1.A(ANODE) J1.2 J1.3 J3.7 J5.1 J5.40 J7.G1(GND) J7.G2(GND) J7.G3(GND) J7.G4(GND) J8.6 J10.3 J11.3 J11.5 J11.7 J11.9 J12.8 J13.G1(GND) J13.G2(GND) J13.G3(GND) J13.G4(GND) J14.3 J14.5 J14.9 J14.15 J14.17 J14.19 J16.8 J21.6 J23.3 J24.1 J24.40 R1.1(CCW) R127.2 R129.2 R130.2 R133.1 R135.1 R138.2 R139.2 R140.2 R142.1 R146.2 R154.2 SW1.B(2) SW2.A(1) SW4.B(2) U3.4(VSS) U4.2(GND) U4.H(TPAD) ; also on sheet 4 5 6 7 8
VCC_FLASH: C66.2 R107.1 U3.8(VCC)
VCC_IO_CAN: C40.2 R131.1 U4.5(VIO)
VDD_POT: J9.2 R1.3(CW) R49.2
VDDA: J9.1 R49.1 ; also on sheet 7
VDDD: R44.1 R109.1 ; also on sheet 7
VIN: R42.1 ; also on sheet 4
VIN_EXP: J1.1 J5.39 J24.2 R42.2
ARD_A0: J2.1 J24.23 ; also on sheet 8
ARD_A1: J2.2 J24.25 ; also on sheet 8
ARD_A2: J2.3 J24.27 ; also on sheet 8
ARD_A3: J2.4 J24.22 ; also on sheet 8
ARD_A4: J2.5 J8.2 J16.1 J21.2 J24.24 ; also on sheet 8
ARD_A5: J2.6 J8.3 J21.3 J24.26 ; also on sheet 8
ARD_A6: J2.7 J24.34 ; also on sheet 8
ARD_A7: J24.20 ; also on sheet 8
ARD_B0: R33.2 R36.1 ; also on sheet 8
ARD_B0_EXP: J24.16 R33.1
ARD_B1: R6.1 R7.2 ; also on sheet 8
ARD_B1_EXP: J24.18 R7.1
ARD_B2: J24.17 ; also on sheet 8
ARD_B3: J24.19 ; also on sheet 8
ARD_B5: J24.28 ; also on sheet 8
ARD_B6: J24.30 ; also on sheet 8
ARD_B7: J2.8 J24.32 ; also on sheet 8
CAN_RX1: R136.1 R137.2 ; also on sheet 8
CAN_STB: R151.2 U4.8(STB)
CAN_TX1: R148.1 R149.2 ; also on sheet 8
DFU_SW1: J19.2 J24.10 ; also on sheet 8
DFU_SW2: J22.2 J24.9 ; also on sheet 8
ETM_TRACE_CLK: J14.12 ; also on sheet 8
ETM_TRACE_D0: J14.14 ; also on sheet 8
ETM_TRACE_D1: J14.16 ; also on sheet 8
ETM_TRACE_D2: J14.18 ; also on sheet 8
ETM_TRACE_D3: J14.20 ; also on sheet 8
HDR_3V3: J1.5 J5.2 J8.7 J16.7 J21.7 J24.39 Q5.S Q7.4(E) R141.2
HDR_5V0: J1.4 J8.1 J12.7 J21.1 Q4.S Q6.4(E) R143.2
HDR_I2C_SCL: J3.10 J5.21 J8.5 J12.5 J21.5 R47.2
HDR_I2C_SDA: J3.9 J5.23 J8.4 J12.6 J21.4 R48.2
I2C_SCL: R47.1 R50.1 R53.2 ; also on sheet 8
I2C_SDA: R48.1 R51.1 R54.2 ; also on sheet 8
KP_I2C_SCL: R53.1 ; also on sheet 6
KP_I2C_SDA: R54.1 ; also on sheet 6
KP_RESET: R25.2 ; also on sheet 6
KP_SWCLK: R37.1 ; also on sheet 6
KP_SWDIO: R39.1 ; also on sheet 6
LPCOMP0_INN: J5.13 ; also on sheet 8
LPCOMP0_INP: J5.19 ; also on sheet 8
LPCOMP1_INN: J5.17 ; also on sheet 8
LPCOMP1_INP: J5.15 ; also on sheet 8
P0_1: J5.5 ; also on sheet 8
P1_0: J24.37 ; also on sheet 8
P1_1: J5.7 ; also on sheet 8
P2_0: R28.2 R29.2 R158.2 ; also on sheet 8
P2_1: R30.2 R31.2 ; also on sheet 8
P3_0: J4.8 J5.24 ; also on sheet 8
P3_1: J5.28 J6.4 J18.4 ; also on sheet 8
P4_4: R23.2 ; also on sheet 8
P4_4_EXP: J5.36 R23.1
P4_5: J5.37 J8.8 J21.8 ; also on sheet 8
P5_0: J24.36 R160.2 ; also on sheet 8
P5_2: J24.35 R136.2
P5_3: J24.33 R148.2
P7_6: J3.1 J5.22 R151.1 ; also on sheet 8
P7_7: J12.2 J24.4 ; also on sheet 8
P8_4: J24.6 R46.2 ; also on sheet 8
P8_5: J24.8 R45.2 ; also on sheet 8
P9_4: J5.11 J6.5 J18.5 R76.2 ; also on sheet 8
P9_5: J5.9 J16.3 R73.2 ; also on sheet 8
PERI_HRPWM_0: R32.2 R34.2 R35.2 ; also on sheet 8
PERI_HRPWM_0_EXP: J5.4 R34.1
PERI_HRPWM_1: R4.2 R5.2 R8.2 ; also on sheet 8
PERI_HRPWM_1_EXP: J5.6 R8.1
PERI_HRPWM_2: J5.8 ; also on sheet 8
PERI_HRPWM_3: J5.10 ; also on sheet 8
POT: R2.2 R3.2 ; also on sheet 8
POT_EXP: J24.21 R3.1
PWM_SHIELD: J8.9 J12.1 J21.9 J24.12 ; also on sheet 8
SPI_CLK_ARD: J3.6 J5.18 J6.6 J16.4 J18.6 ; also on sheet 8
SPI_CLK_FLASH: U3.6(SCK) ; also on sheet 8
SPI_CS01_ARD: J3.3 J5.16 ; also on sheet 8
SPI_CS_FLASH: U3.1(CS#) ; also on sheet 8
SPI_MISO_ARD: J3.5 J5.20 J6.8 J16.5 J18.8 ; also on sheet 8
SPI_MISO_FLASH: U3.2(SO/IO1) ; also on sheet 8
SPI_MOSI_ARD: J3.4 J5.14 J6.7 J16.6 J18.7 ; also on sheet 8
SPI_MOSI_FLASH: U3.5(SI/IO0) ; also on sheet 8
TCLK_SWCLK: J11.4 J14.4 R38.1 R59.1
TCLK_SWCLK_MCU: R37.2 R38.2 ; also on sheet 8
TCPWM1_COMPL_EXP: J4.6 J5.34 R15.1
TCPWM1_COMPL_EXP_MCU: R15.2 ; also on sheet 8
TCPWM1_EXP: J4.4 J5.35 R19.1
TCPWM1_EXP_MCU: R19.2 ; also on sheet 8
TCPWM2_COMPL_EXP_MCU: J24.3 ; also on sheet 8
TCPWM2_EXP_MCU: J5.25 ; also on sheet 8
TCPWM_518: J24.14 R28.1
TCPWM_518_COMPL: J24.11 R30.1
TCPWM_COMPL_EXP: J3.2 J5.32 R9.1
TCPWM_COMPL_EXP_MCU: R9.2 ; also on sheet 8
TCPWM_EXP: J4.7 J5.33 R11.1
TCPWM_EXP_MCU: R11.2 ; also on sheet 8
TDI: J11.8 J14.8 R29.1 R52.1
TDO: J11.6 J14.6 R31.1
TMS_SWDIO: J11.2 J14.2 R40.1 R60.1
TMS_SWDIO_MCU: R39.2 R40.2 ; also on sheet 8
UART_1_RX: R63.1 ; also on sheet 6
UART_1_RX_EXP: J24.7 R58.1
UART_1_TX: R56.1 ; also on sheet 6
UART_1_TX_EXP: J24.5 R65.1
UART_CTS_1: J4.5 J24.29 ; also on sheet 8
UART_RTS_1: J4.3 J24.31 ; also on sheet 8
UART_RX: J10.2 R56.2 R57.1 R58.2 ; also on sheet 8
UART_RX_0_MIK: J4.1 J5.31 J6.1 J12.3 J18.1 ; also on sheet 8
UART_TX: J10.1 R63.2 R64.1 R65.2 ; also on sheet 8
UART_TX_0_MIK: J4.2 J5.29 J6.2 J12.4 J18.2 ; also on sheet 8
USER_SWITCH: C43.1 R44.2 R158.1 SW2.B(2)
VOUT_3V3: Q5.D Q7.1(E) R141.1 ; also on sheet 4 5 6 7
VOUT_5V0: C41.2 Q4.D Q6.1(E) R143.1 U4.3(VCC) ; also on sheet 5
VREFH: J3.8 J24.15 ; also on sheet 7
VTARG_DEBUG: C52.1 D1.K(CATHODE) J11.1 J14.1 Q8.S Q9.4(E) R52.2 R59.2 R60.2 R147.2
VTARG_REF: J1.7 LED1.A(ANODE) LED2.A(ANODE) Q8.D Q9.1(E) R43.1 R50.2 R51.2 R57.2 R64.2 R73.1 R76.1 R107.2 R128.1 R131.2 R147.1 R153.1 ; also on sheet 4 6 8
XRES_L_MCU: C67.1 J1.6 J5.30 J6.3 J11.10 J14.10 J16.2 J18.3 R25.1 R109.2 SW1.A(1) ; also on sheet 7
N22092982: Q8.G Q9.3(C) R146.1
N22093014: Q9.2(B) Q9.5(B) R142.2
N22093052: Q9.6(C) R138.1
N22173555: C25.2 R35.1 R36.2 TP5.1(TP)
N22173666: C1.2 R5.1 R6.2 TP3.1(TP)
N22184104: Q4.G Q6.3(C) R139.1
N22184124: Q5.G Q7.3(C) R140.1
N22184135: Q6.2(B) Q6.5(B) R133.2
N22184141: Q7.2(B) Q7.5(B) R135.2
N22184147: Q6.6(C) R127.1
N22184151: Q7.6(C) R130.1
N22185312: C42.1 R1.2(WIPER) R2.1
N22190096: J24.38 R43.2 R160.1 SW4.A(1)
N22190335: LED2.K(CATHODE) R46.1
N22190371: LED1.K(CATHODE) R45.1
N22190519: J19.1 R128.2
N22190521: J22.1 R153.2
N22190557: J19.3 R129.1
N22190561: J22.3 R154.1
N22248472: J13.S(RF_IN) R32.1
N22248626: J7.S(RF_IN) R4.1
N22257092: C94.2 J23.1 R144.1 R152.1 U4.6(CANL)
N22257130: C94.1 J23.2 R145.2 R152.2 U4.7(CANH)
N22257140: C93.1 R144.2 R145.1
N22258155: R149.1 U4.1(TxD)
N22258259: R137.1 U4.4(RxD)

Not connected (* = marked no-connect by the designer): J1 8*; J5 3 12 26 27 38; J14 7* 11* 13*; J24 13; U3 3(WP#/IO2)* 7(IO3/RESET#)*

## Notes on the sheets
sheet 9
- KitProg3 I2C Interface
- BOY-II Device 10-pin SWD/JTAG Header
- ETM Header
- KitProg3 Primary UART Interface
- UART header
- VTARG_REF Reverse Voltage Protection
sheet 10
- CAN FD Transceiver
- NOR Flash(Optional)
sheet 11
- Arduino Headers
- mikroBUS Headers
- Shield2Go Interface
- S2GO1
- Pin1
- Pin10
- Reverse Voltage Protection for Arduino Power
- Pin17
- Pin9
- Shield2Go Interface
- S2GO2
- Pin1
- Pin10
- Pin17
- Pin9
- CS#
- CS#
sheet 12
- Expansion Headers-2
- Expansion Headers-1
- USER BTN-1
- NOTE: MOTOR CONTROL LITE KIT COMPATIBLE HEADERS
- Reset Button
- DFU Selection Jumper
- User/Hibernate switch
- USER BTN-2
- SW1
- User LEDs
- Default position is 2 & 3  for J19 and J22
sheet 13
- HRPWM Output_1
- Potentiometer
- Tri pads
- Quad pads
- RC VALUES ARE PLACEHOLDER
- Tri pads
- HRPWM Output_2
- Quad pads
- RC VALUES ARE PLACEHOLDER
- Tri pads
sheet 14
- REVISION HISTORY
- REV
- ORIG. OF
  CHANGE
- DATE
- DESCRIPTION OF CHANGE
- 0.01
- Preliminary release
- RAJB
- 11/08/2023
- 0.2
- Updated as per the latest requirement and SAS pinout
- RAJB
- 16/11/2023
- 0.3
- Updated as per the latest requirement
- RAJB
- 30/11/2023
- 0.4
- Changed the Hybernate switch logic and Power switch, SPI Flash is added.
- RAJB
- 08/12/2023
- 0.5
- Pin mapping changed in Expandion connector, Hybernate switch changed to previous logic
- RAJB
- 12/12/2023
- 0.6
- Added R195, changed the package of c87, c88 net name change
- RAJB
- 13/12/2023
- 0.7
- Hardfixed the Switch refdes locations
- RAJB
- 18/12/2023
- 0.8
- Back annotated
- RAJB
- 20/12/2023
- 0.9
- VSS and GND net shorted for SMA connector
- RAJB
- 29/01/2024
- 1.0
- Added 100K resistor on load switch enable and BDRB comments addressed, SW5 removed from the design
- RAJB
- 02/02/2024
- 1.1
- LED1,2,3,4 colors changed as per the Marketing team requirement and Expansion header made stuff ,
  P9_0 text added for information, Changed R98 to 500-60433-01
- RAJB
- 19/03/2024
- 3.0
- Updated ETM trace port, POT connection, DFU PU changed Regulator to LM3940
- RAJB
- 21/08/2024
- 4.0
- VAREF part changed to 0.22uF as per JIRA, BD updated, Changed SW4 to USER Button -1 , DFU PU changed to 1K
  Changed R84 to 330E
- RAJB
- 10/09/2024
- 16/09/2024
- 5.0
- Silk screen changed and revised to allign with Layout as 5.0
- RAJB
- 08/11/2024
